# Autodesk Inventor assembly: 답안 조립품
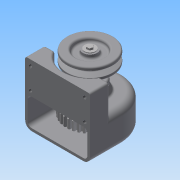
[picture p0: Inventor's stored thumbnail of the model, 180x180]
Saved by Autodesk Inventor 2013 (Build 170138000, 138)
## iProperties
Created: 2015-03
Part Number: 답안 조립품
Document SubType Name: Assembly
Designer: Administrator
Author: Administrator
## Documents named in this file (14)
- C:\Documents and Settings\Administrator\바탕 화면\450214V1003\답안 조립품.iam
- C:\Documents and Settings\Administrator\바탕 화면\450214V1003\1-본체.ipt
- C:\Documents and Settings\Administrator\바탕 화면\450214V1003\베어링 6001.ipt
- C:\Documents and Settings\Administrator\바탕 화면\450214V1003\축.ipt
- C:\Documents and Settings\Administrator\바탕 화면\450214V1003\5-스퍼기어.ipt
- C:\Documents and Settings\Administrator\바탕 화면\450214V1003\키5x5.ipt
- C:\Documents and Settings\Administrator\바탕 화면\450214V1003\축커버.ipt
- C:\Documents and Settings\Administrator\바탕 화면\450214V1003\키4x4.ipt
- C:\Documents and Settings\Administrator\바탕 화면\450214V1003\오일실.ipt
- C:\Documents and Settings\Administrator\바탕 화면\450214V1003\M3x0.5.ipt
- C:\Documents and Settings\Administrator\바탕 화면\450214V1003\4-V벨트풀리.ipt
- C:\Documents and Settings\Administrator\바탕 화면\450214V1003\와샤.ipt
- C:\Documents and Settings\Administrator\바탕 화면\450214V1003\M5x0.8.ipt
- M5x0.8.ipt
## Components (7 placed, 4 different names)
1. 1-본체:1
2. 4-V벨트풀리:1 — 플러쉬:1, 각도:4
3. M5x0.8:1 — 각도:5
4. M3x0.5:1
5. M3x0.5:2
6. M3x0.5:3
7. M3x0.5:4
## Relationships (3: Angle 2, Flush 1)
- 플러쉬:1 [Flush]: 4-V벨트풀리:1
- 각도:4 [Angle]: 4-V벨트풀리:1
- 각도:5 [Angle]: M5x0.8:1
